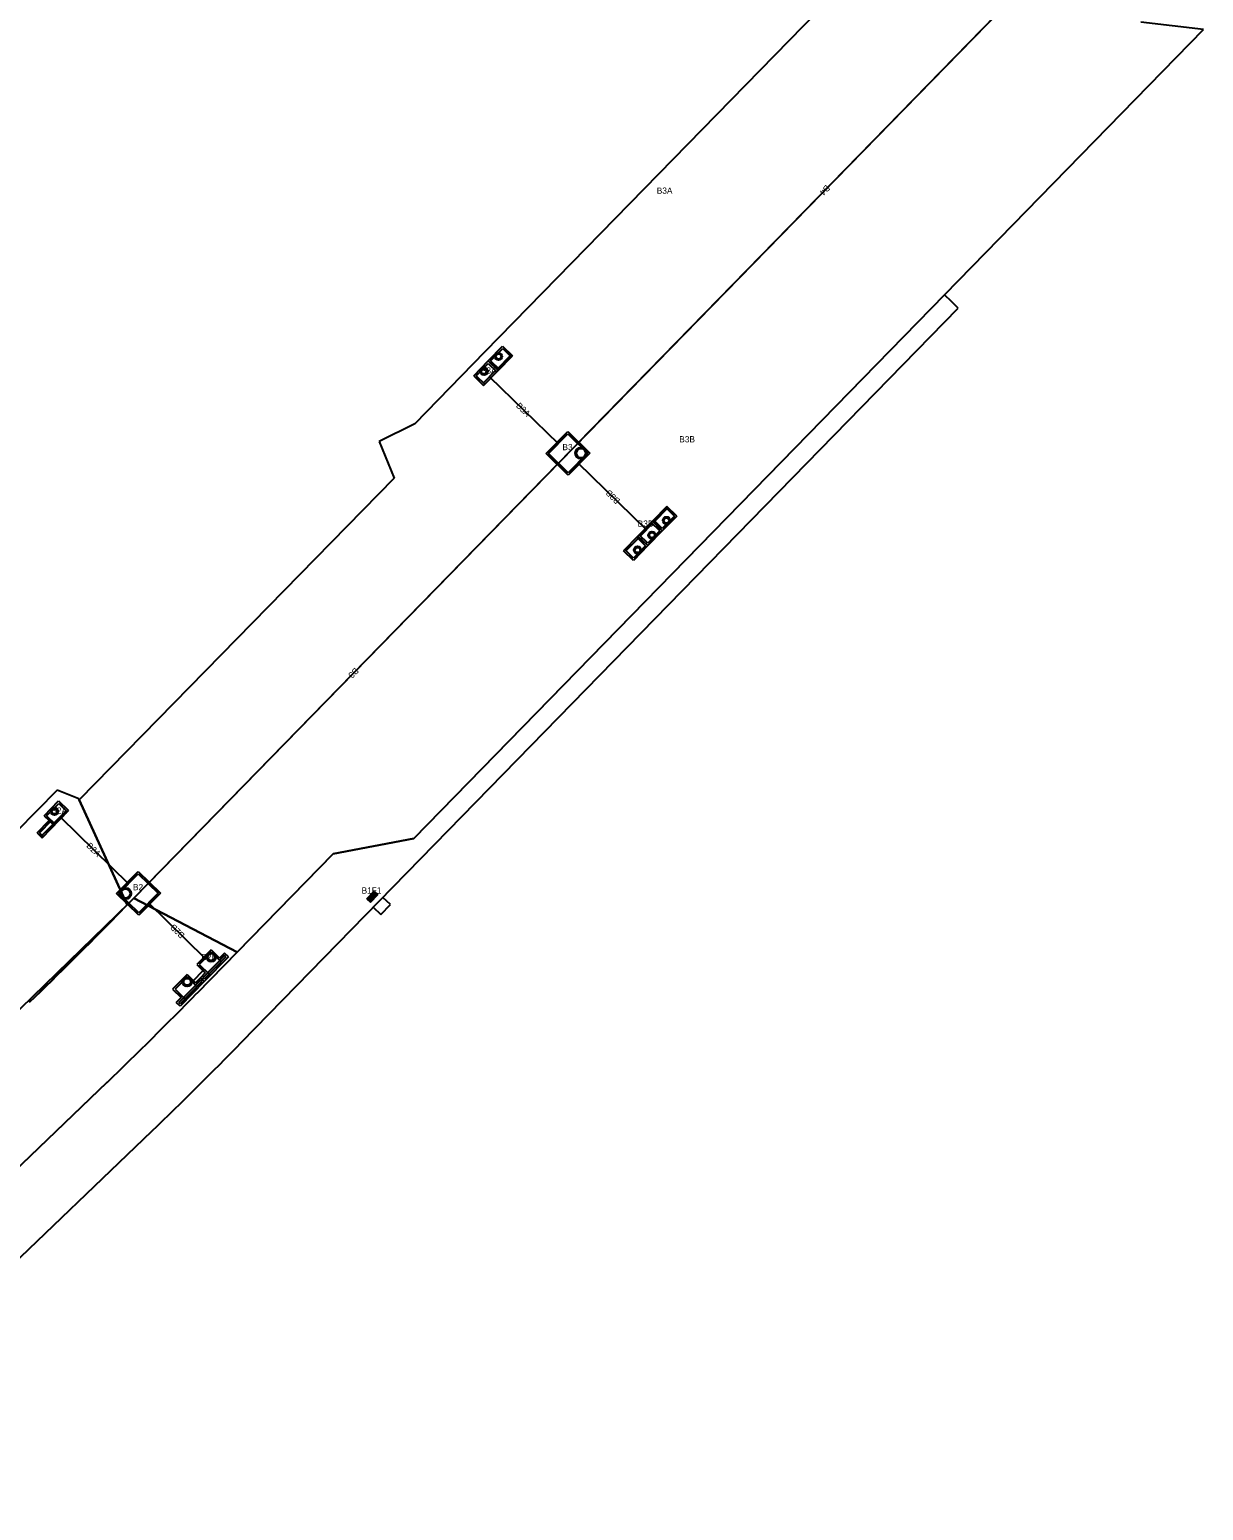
# Model space of a CAD drawing. Extents: x 2254979 to 2278074, y 13790855 to 13792793.
# Drawn here: x 2255367.3 to 2255707.4, y 13791090 to 13791519.1 of the extents above; entities that cross this region are included whole.
import ezdxf

# ---------------------------------------------------------------- set-up
doc = ezdxf.new("R2010")
doc.units = 0
for name, color, linetype in [('D_DRAIN_MISC', 7, 'Continuous'), ('D_DRAIN_NOTES_1', 7, 'Continuous'), ('D_DRN_AREA_X', 7, 'Continuous'), ('D_DRN_PIPE', 7, 'Continuous'), ('D_INLET_1', 7, 'Continuous'), ('D_INLET_2', 7, 'Continuous'), ('D_PIPES_1', 7, 'Continuous'), ('D_RDWY_CONC_RIPRAP', 7, 'Continuous')]:
    doc.layers.add(name, color=color, linetype=linetype)

msp = doc.modelspace()

# ---------------------------------------------------------------- linework, layer by layer
at = {"layer": 'D_DRAIN_MISC'}
for p, q in [((2255502.64, 13791424.91), (2255502.64, 13791424.91)), ((2255505.46, 13791425.65), (2255505.46, 13791425.65)), ((2255498.45, 13791420.62), (2255498.45, 13791420.62)), ((2255501.62, 13791421.72), (2255501.62, 13791421.72)), ((2255504.79, 13791422.82), (2255504.79, 13791422.82)), ((2255497.78, 13791417.78), (2255497.78, 13791417.78)), ((2255500.6, 13791418.52), (2255500.6, 13791418.52)), ((2255520.46, 13791399.14), (2255520.46, 13791399.14)), ((2255526.11, 13791399.21), (2255526.11, 13791399.21)), ((2255523.32, 13791396.35), (2255523.32, 13791396.35)), ((2255520.53, 13791393.48), (2255520.53, 13791393.48)), ((2255526.18, 13791393.55), (2255526.18, 13791393.55)), ((2255550.23, 13791378.47), (2255550.23, 13791378.47)), ((2255553.05, 13791379.21), (2255553.05, 13791379.21)), ((2255546.04, 13791374.17), (2255546.04, 13791374.17)), ((2255547.12, 13791373.12), (2255547.12, 13791373.12)), ((2255552.38, 13791376.37), (2255552.38, 13791376.37)), ((2255541.85, 13791369.88), (2255541.85, 13791369.88)), ((2255548.19, 13791372.08), (2255548.19, 13791372.08)), ((2255541.18, 13791367.04), (2255541.18, 13791367.04)), ((2255544, 13791367.78), (2255544, 13791367.78)), ((2255373.99, 13791293.08), (2255373.99, 13791293.08)), ((2255375.07, 13791292.03), (2255375.07, 13791292.03)), ((2255376.81, 13791293.82), (2255376.81, 13791293.82)), ((2255373.32, 13791290.24), (2255373.32, 13791290.24)), ((2255376.14, 13791290.98), (2255376.14, 13791290.98)), ((2255396, 13791271.6), (2255396, 13791271.6)), ((2255401.66, 13791271.67), (2255401.66, 13791271.67)), ((2255396.07, 13791265.95), (2255396.07, 13791265.95)), ((2255398.86, 13791268.81), (2255398.86, 13791268.81)), ((2255401.73, 13791266.02), (2255401.73, 13791266.02)), ((2255465.59, 13791266.79), (2255465.59, 13791266.79)), ((2255466.62, 13791267.84), (2255466.62, 13791267.84)), ((2255467.64, 13791268.89), (2255467.64, 13791268.89)), ((2255418.19, 13791249.95), (2255418.19, 13791249.95)), ((2255421.36, 13791250.34), (2255421.36, 13791250.34)), ((2255417.87, 13791246.77), (2255417.87, 13791246.77)), ((2255419.62, 13791248.56), (2255419.62, 13791248.56)), ((2255421.05, 13791247.16), (2255421.05, 13791247.16)), ((2255411.2, 13791242.8), (2255411.2, 13791242.8)), ((2255412.63, 13791241.4), (2255412.63, 13791241.4)), ((2255414.38, 13791243.19), (2255414.38, 13791243.19)), ((2255410.89, 13791239.61), (2255410.89, 13791239.61)), ((2255414.07, 13791240), (2255414.07, 13791240))]:
    msp.add_line(p, q, dxfattribs=at)
msp.add_circle((2255466.62, 13791267.84), 0.25, dxfattribs=at)
at = {"layer": 'D_DRN_AREA_X'}
for p, q in [((2255683.04, 13791560.02), (2255397.55, 13791267.46)), ((2255617.8, 13791547.21), (2255499.14, 13791425.62)), ((2255478.69, 13791284.75), (2255707.42, 13791519.14)), ((2255707.42, 13791519.14), (2255689.25, 13791521.28)), ((2255634.41, 13791440.3), (2255632.4, 13791442.27)), ((2255428.73, 13791225.69), (2255636.34, 13791438.43)), ((2255636.34, 13791438.43), (2255634.41, 13791440.3)), ((2255499.14, 13791425.62), (2255478.9, 13791404.85)), ((2255478.9, 13791404.85), (2255468.61, 13791399.79)), ((2255468.61, 13791399.79), (2255472.95, 13791389.15)), ((2255472.95, 13791389.15), (2255381.67, 13791295.92)), ((2255375.34, 13791298.76), (2255354.02, 13791277.09)), ((2255381.56, 13791296.18), (2255375.34, 13791298.76)), ((2255381.67, 13791295.92), (2255381.56, 13791296.18)), ((2255395.6, 13791265.47), (2255381.67, 13791295.92)), ((2255381.67, 13791295.92), (2255395.6, 13791265.47)), ((2255455.25, 13791280.3), (2255478.69, 13791284.75)), ((2255455.25, 13791280.3), (2255427.42, 13791251.78)), ((2255427.42, 13791251.78), (2255455.25, 13791280.3)), ((2255397.55, 13791267.46), (2255395.6, 13791265.47)), ((2255427.42, 13791251.78), (2255397.55, 13791267.46)), ((2255397.55, 13791267.46), (2255427.42, 13791251.78)), ((2255392.67, 13791262.46), (2255395.6, 13791265.47)), ((2255395.6, 13791265.47), (2255392.67, 13791262.46)), ((2255427.42, 13791251.78), (2255415.82, 13791239.89)), ((2255415.82, 13791239.89), (2255427.42, 13791251.78)), ((2255427.42, 13791251.78), (2255427.42, 13791251.78)), ((2255427.42, 13791251.78), (2255427.42, 13791251.78)), ((2255389.76, 13791214.04), (2255302.38, 13791130.12)), ((2255302.38, 13791130.12), (2255389.76, 13791214.04)), ((2255288.25, 13791089.98), (2255402.69, 13791199.88))]:
    msp.add_line(p, q, dxfattribs=at)
for points in [[(2255395.6, 13791265.47), (2255397.55, 13791267.46), (2255683.04, 13791560.02)], [(2255632.4, 13791442.27), (2255478.69, 13791284.75), (2255455.25, 13791280.3)]]:
    msp.add_lwpolyline(points, dxfattribs=at)
for centre, radius, start, end in [((2254605.4, 13792030.71), 1100, 313.84074, 315.70035), ((2254605.4, 13792030.71), 1100, 313.84074, 315.69373), ((2254605.4, 13792030.71), 1100, 315.69373, 315.70035), ((2254606.36, 13792029.79), 1131, 313.84074, 315.70035), ((2254606.36, 13792029.79), 1131, 313.84074, 315.70035), ((2254593.41, 13792042.58), 1168.37, 313.84074, 315.63907)]:
    msp.add_arc(centre, radius, start, end, dxfattribs=at)
at = {"layer": 'D_DRN_PIPE'}
for p, q in [((2255669.15, 13791545.78), (2255526.11, 13791399.21)), ((2255500.6, 13791418.52), (2255520.46, 13791399.14)), ((2255520.53, 13791393.48), (2255401.66, 13791271.67)), ((2255546.04, 13791374.17), (2255526.18, 13791393.55)), ((2255376.14, 13791290.98), (2255396, 13791271.6)), ((2255396.07, 13791265.95), (2255276.86, 13791150.44)), ((2255418.19, 13791249.95), (2255401.73, 13791266.02))]:
    msp.add_line(p, q, dxfattribs=at)
at = {"layer": 'D_INLET_1'}
for p, q in [((2255500.19, 13791423.11), (2255504.38, 13791427.41)), ((2255500.89, 13791423.12), (2255504.39, 13791426.7)), ((2255503.04, 13791421.03), (2255506.53, 13791424.6)), ((2255503.05, 13791420.32), (2255507.24, 13791424.61)), ((2255504.38, 13791427.41), (2255507.24, 13791424.61)), ((2255504.39, 13791426.7), (2255506.89, 13791424.26)), ((2255496, 13791418.82), (2255500.19, 13791423.11)), ((2255496.7, 13791418.83), (2255500.2, 13791422.41)), ((2255498.85, 13791416.73), (2255502.34, 13791420.31)), ((2255498.86, 13791416.02), (2255503.05, 13791420.32)), ((2255500.19, 13791423.11), (2255503.05, 13791420.32)), ((2255500.19, 13791423.11), (2255503.05, 13791420.32)), ((2255500.19, 13791423.11), (2255503.05, 13791420.32)), ((2255500.19, 13791423.11), (2255503.05, 13791420.32)), ((2255500.2, 13791422.41), (2255502.7, 13791419.96)), ((2255500.89, 13791423.12), (2255503.4, 13791420.68)), ((2255496, 13791418.82), (2255498.86, 13791416.02)), ((2255496.7, 13791418.83), (2255499.21, 13791416.38)), ((2255516.96, 13791396.27), (2255523.24, 13791402.71)), ((2255517.66, 13791396.28), (2255523.25, 13791402)), ((2255523.24, 13791402.71), (2255529.68, 13791396.42)), ((2255523.25, 13791402), (2255528.98, 13791396.42)), ((2255523.4, 13791389.98), (2255516.96, 13791396.27)), ((2255523.39, 13791390.69), (2255517.66, 13791396.28)), ((2255528.98, 13791396.42), (2255523.39, 13791390.69)), ((2255529.68, 13791396.42), (2255523.4, 13791389.98)), ((2255551.97, 13791380.96), (2255547.78, 13791376.67)), ((2255551.98, 13791380.26), (2255548.49, 13791376.68)), ((2255554.83, 13791378.17), (2255550.64, 13791373.87)), ((2255554.13, 13791378.16), (2255550.64, 13791374.58)), ((2255554.13, 13791378.16), (2255551.62, 13791380.6)), ((2255554.83, 13791378.17), (2255551.97, 13791380.96)), ((2255547.78, 13791376.67), (2255543.59, 13791372.37)), ((2255547.79, 13791375.96), (2255544.3, 13791372.38)), ((2255549.94, 13791373.87), (2255546.44, 13791370.29)), ((2255550.64, 13791373.87), (2255546.45, 13791369.58)), ((2255549.94, 13791373.87), (2255547.43, 13791376.31)), ((2255550.64, 13791373.87), (2255547.78, 13791376.67)), ((2255550.64, 13791373.87), (2255547.78, 13791376.67)), ((2255550.64, 13791374.58), (2255548.13, 13791377.03)), ((2255543.59, 13791372.37), (2255539.4, 13791368.08)), ((2255543.6, 13791371.67), (2255540.11, 13791368.09)), ((2255545.75, 13791369.57), (2255542.25, 13791365.99)), ((2255546.45, 13791369.58), (2255542.26, 13791365.29)), ((2255545.75, 13791369.57), (2255543.24, 13791372.02)), ((2255546.45, 13791369.58), (2255543.59, 13791372.37)), ((2255546.45, 13791369.58), (2255543.59, 13791372.37)), ((2255546.44, 13791370.29), (2255543.94, 13791372.73)), ((2255542.26, 13791365.29), (2255539.4, 13791368.08)), ((2255542.25, 13791365.99), (2255539.75, 13791368.44)), ((2255370.9, 13791285.62), (2255377.89, 13791292.77)), ((2255370.91, 13791284.91), (2255378.59, 13791292.78)), ((2255371.54, 13791291.28), (2255375.73, 13791295.58)), ((2255372.25, 13791291.29), (2255375.74, 13791294.87)), ((2255375.73, 13791295.58), (2255378.59, 13791292.78)), ((2255375.74, 13791294.87), (2255378.24, 13791292.42)), ((2255369.48, 13791286.31), (2255372.97, 13791289.88)), ((2255370.19, 13791286.31), (2255373.68, 13791289.89)), ((2255371.54, 13791291.28), (2255372.97, 13791289.88)), ((2255372.25, 13791291.29), (2255374.75, 13791288.85)), ((2255372.97, 13791289.88), (2255374.4, 13791288.49)), ((2255369.48, 13791286.31), (2255370.91, 13791284.91)), ((2255370.19, 13791286.31), (2255371.26, 13791285.27)), ((2255392.5, 13791268.73), (2255398.79, 13791275.17)), ((2255393.21, 13791268.74), (2255398.79, 13791274.47)), ((2255398.79, 13791275.17), (2255405.23, 13791268.89)), ((2255398.79, 13791274.47), (2255404.52, 13791268.88)), ((2255398.94, 13791262.45), (2255392.5, 13791268.73)), ((2255398.93, 13791263.15), (2255393.21, 13791268.74)), ((2255404.52, 13791268.88), (2255398.93, 13791263.15)), ((2255405.23, 13791268.89), (2255398.94, 13791262.45)), ((2255419.92, 13791252.45), (2255415.73, 13791248.15)), ((2255419.93, 13791251.74), (2255416.44, 13791248.16)), ((2255423.78, 13791250.78), (2255417.49, 13791244.34)), ((2255424.19, 13791250.38), (2255417.91, 13791243.94)), ((2255424.9, 13791250.39), (2255417.92, 13791243.23)), ((2255419.92, 13791252.45), (2255422.37, 13791250.06)), ((2255419.93, 13791251.74), (2255422.8, 13791248.95)), ((2255423.77, 13791251.49), (2255422.37, 13791250.06)), ((2255424.9, 13791250.39), (2255423.77, 13791251.49)), ((2255424.19, 13791250.38), (2255423.78, 13791250.78)), ((2255412.94, 13791245.29), (2255408.75, 13791241)), ((2255412.95, 13791244.58), (2255409.46, 13791241.01)), ((2255412.94, 13791245.29), (2255415.39, 13791242.9)), ((2255412.95, 13791244.58), (2255415.81, 13791241.79)), ((2255415.73, 13791248.15), (2255418.18, 13791245.77)), ((2255416.44, 13791248.16), (2255419.3, 13791245.37)), ((2255418.18, 13791245.77), (2255416.79, 13791244.33)), ((2255408.75, 13791241), (2255411.2, 13791238.61)), ((2255409.46, 13791241.01), (2255412.32, 13791238.21)), ((2255416.79, 13791243.63), (2255410.51, 13791237.19)), ((2255417.21, 13791243.22), (2255410.92, 13791236.78)), ((2255417.92, 13791243.23), (2255410.93, 13791236.07)), ((2255416.79, 13791244.33), (2255415.39, 13791242.9)), ((2255417.92, 13791243.23), (2255416.79, 13791244.33)), ((2255417.92, 13791243.23), (2255416.79, 13791244.33)), ((2255417.21, 13791243.22), (2255416.79, 13791243.63)), ((2255417.91, 13791243.94), (2255417.49, 13791244.34)), ((2255411.2, 13791238.61), (2255409.8, 13791237.18)), ((2255410.93, 13791236.07), (2255409.8, 13791237.18)), ((2255410.92, 13791236.78), (2255410.51, 13791237.19))]:
    msp.add_line(p, q, dxfattribs=at)
for centre, radius in [((2255503.18, 13791424.39), 1.08), ((2255503.18, 13791424.39), 0.75), ((2255498.99, 13791420.09), 1.08), ((2255498.99, 13791420.09), 0.75), ((2255527.09, 13791396.39), 1.67), ((2255527.09, 13791396.39), 1.33), ((2255551.84, 13791376.89), 1.08), ((2255551.84, 13791376.89), 0.75), ((2255547.65, 13791372.6), 1.08), ((2255547.65, 13791372.6), 0.75), ((2255543.46, 13791368.31), 1.08), ((2255543.46, 13791368.31), 0.75), ((2255374.53, 13791292.56), 1.08), ((2255374.53, 13791292.56), 0.75), ((2255395.09, 13791268.76), 1.67), ((2255395.09, 13791268.76), 1.33), ((2255419.95, 13791250.33), 1.33), ((2255419.95, 13791250.33), 1), ((2255412.97, 13791243.17), 1.33), ((2255412.97, 13791243.17), 1)]:
    msp.add_circle(centre, radius, dxfattribs=at)
at = {"layer": 'D_INLET_2'}
for p, q in [((2255465, 13791267.23), (2255467.19, 13791269.47)), ((2255465, 13791267.23), (2255466.05, 13791266.21)), ((2255465.21, 13791267.17), (2255467.26, 13791269.27)), ((2255465.21, 13791267.17), (2255465.98, 13791266.42)), ((2255465.22, 13791267.18), (2255465.99, 13791266.43)), ((2255465.26, 13791267.22), (2255466.03, 13791266.47)), ((2255465.38, 13791267.34), (2255466.14, 13791266.59)), ((2255465.41, 13791267.38), (2255466.18, 13791266.63)), ((2255465.52, 13791266.72), (2255467.71, 13791268.96)), ((2255465.53, 13791267.49), (2255466.3, 13791266.75)), ((2255465.57, 13791267.53), (2255466.33, 13791266.78)), ((2255465.68, 13791267.65), (2255466.45, 13791266.9)), ((2255465.72, 13791267.69), (2255466.49, 13791266.94)), ((2255465.84, 13791267.81), (2255466.6, 13791267.06)), ((2255465.87, 13791267.85), (2255466.64, 13791267.1)), ((2255465.98, 13791266.42), (2255468.03, 13791268.52)), ((2255465.99, 13791267.97), (2255466.76, 13791267.22)), ((2255466.03, 13791268), (2255466.79, 13791267.25)), ((2255466.05, 13791266.21), (2255468.23, 13791268.46)), ((2255466.1, 13791268.35), (2255467.14, 13791267.33)), ((2255466.14, 13791268.12), (2255466.91, 13791267.37)), ((2255466.18, 13791268.16), (2255466.95, 13791267.41)), ((2255466.29, 13791268.27), (2255467.06, 13791267.53)), ((2255466.33, 13791268.31), (2255467.09, 13791267.56)), ((2255466.44, 13791268.43), (2255467.21, 13791267.68)), ((2255466.48, 13791268.47), (2255467.25, 13791267.72)), ((2255466.6, 13791268.59), (2255467.36, 13791267.84)), ((2255466.63, 13791268.63), (2255467.4, 13791267.88)), ((2255466.75, 13791268.74), (2255467.52, 13791268)), ((2255466.79, 13791268.78), (2255467.55, 13791268.03)), ((2255466.9, 13791268.9), (2255467.67, 13791268.15)), ((2255466.94, 13791268.94), (2255467.71, 13791268.19)), ((2255467.05, 13791269.06), (2255467.82, 13791268.31)), ((2255467.09, 13791269.1), (2255467.86, 13791268.35)), ((2255467.19, 13791269.47), (2255468.23, 13791268.46)), ((2255467.21, 13791269.21), (2255467.98, 13791268.47)), ((2255467.24, 13791269.25), (2255468.01, 13791268.5)), ((2255467.26, 13791269.27), (2255468.03, 13791268.52))]:
    msp.add_line(p, q, dxfattribs=at)
msp.add_circle((2255466.62, 13791267.84), 0.303, dxfattribs=at)
at = {"layer": 'D_PIPES_1'}
msp.add_line((2255414.38, 13791243.19), (2255417.87, 13791246.77), dxfattribs=at)
at = {"layer": 'D_RDWY_CONC_RIPRAP'}
for p, q in [((2255469.68, 13791267.64), (2255466.89, 13791264.78)), ((2255471.84, 13791265.54), (2255469.68, 13791267.64)), ((2255466.89, 13791264.78), (2255469.05, 13791262.67)), ((2255469.05, 13791262.67), (2255471.84, 13791265.54))]:
    msp.add_line(p, q, dxfattribs=at)

# ---------------------------------------------------------------- texts
at = {"layer": 'D_DRAIN_NOTES_1'}
for s, p in [('B3A', (2255549.04, 13791471.57)), ('B3A', (2255498.07, 13791419.42)), ('B3', (2255521.71, 13791397.25)), ('B3B', (2255555.56, 13791399.51)), ('B3B', (2255543.51, 13791375.07)), ('B2A', (2255373.62, 13791291.88)), ('B2', (2255397.26, 13791269.71)), ('B1F1', (2255463.51, 13791268.74)), ('B2B', (2255417.08, 13791249.46))]:
    msp.add_text(s, height=1.8, dxfattribs=at).set_placement(p)
for s, rotation, p in [('B4', 225.7003, (2255598.11, 13791474.27)), ('B3A', 315.7003, (2255508.09, 13791409.95)), ('B3B', 135.7003, (2255538.56, 13791382.74)), ('B3', 225.7003, (2255461.57, 13791334.36)), ('B2A', 315.7003, (2255383.64, 13791282.41)), ('B2B', 135.7003, (2255412.4, 13791256.86))]:
    msp.add_text(s, height=1.8, rotation=rotation, dxfattribs=at).set_placement(p)

doc.saveas('drawing.dxf')
